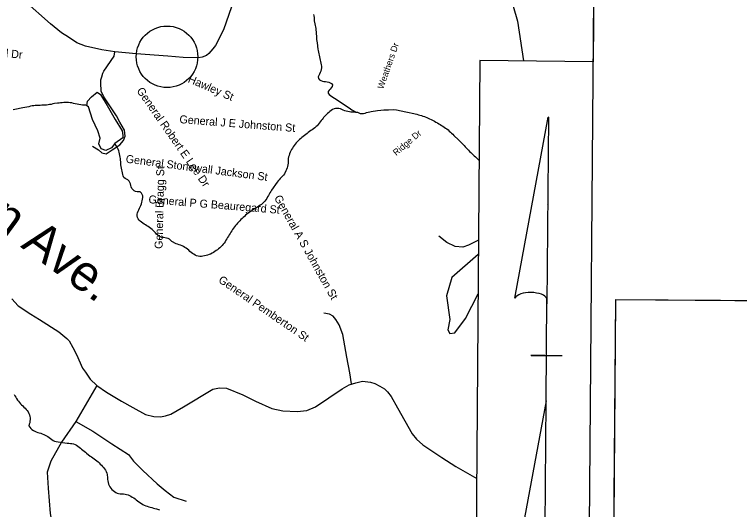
# Model space of a CAD drawing. Extents: x 1379453 to 1387082, y 594364 to 596664.
# Drawn here: x 1380505.6 to 1380802.6, y 595868.7 to 596071.5 of the extents above; entities that cross this region are included whole.
import ezdxf

# ---------------------------------------------------------------- set-up
doc = ezdxf.new("R2010")
doc.units = 0
for name, color, linetype in [('Old_Level_1', 7, 'Continuous'), ('Old_Level_10', 7, 'Continuous'), ('Old_Level_11', 7, 'Continuous'), ('Old_Level_31', 7, 'Continuous'), ('Old_Level_32', 7, 'Continuous'), ('Old_Level_35', 7, 'Continuous'), ('Old_Level_50', 7, 'Continuous'), ('Old_Level_59', 7, 'Continuous'), ('Old_Level_60', 7, 'Continuous'), ('Old_Level_62', 7, 'Continuous'), ('Prop North Arrow for Plan Sheets CELL', 7, 'Continuous'), ('Sheet Clip Boundary CELL', 7, 'Continuous')]:
    doc.layers.add(name, color=color, linetype=linetype)

msp = doc.modelspace()

# ---------------------------------------------------------------- linework, layer by layer
at = {"layer": 'Old_Level_1'}
msp.add_line((1380745.81, 596434.81), (1380740.66, 595820.56), dxfattribs=at)
at = {"layer": 'Old_Level_31'}
msp.add_line((1380723.86, 595993.71), (1380723.86, 595993.71), dxfattribs=at)
at = {"layer": 'Old_Level_32'}
for points in [[(1380690.45, 596156.89), (1380691.25, 596150.45), (1380692.03, 596143.95), (1380693.97, 596136.6), (1380696.43, 596125.28), (1380699.09, 596114.97), (1380701.97, 596103.75), (1380703.91, 596095.29), (1380705.73, 596089.1), (1380708.34, 596080.29), (1380711.67, 596068.72), (1380714.14, 596052.46)], [(1380594.44, 596074.6), (1380592.23, 596068.33), (1380591.17, 596065.24), (1380587.93, 596058.83), (1380586.84, 596057.4), (1380585.12, 596055.55), (1380584.19, 596054.73), (1380582.44, 596054.02), (1380580.92, 596053.71), (1380574.65, 596053.92), (1380568.42, 596054.42), (1380555.47, 596055.44), (1380546.72, 596056.16), (1380541.28, 596057.06), (1380534.67, 596058.53), (1380531.08, 596059.96), (1380527.63, 596062.24), (1380524.79, 596064.03), (1380520.37, 596067.67), (1380509.57, 596077.25)], [(1380504.4, 595955.07), (1380507.06, 595952.16), (1380512.24, 595948.74), (1380515.84, 595946.5), (1380523.75, 595941.56), (1380527.06, 595938.8), (1380527.97, 595937.78), (1380529.42, 595935.04), (1380530.94, 595932.25), (1380533.36, 595926.58), (1380534.67, 595924.97), (1380536.49, 595922.17), (1380539.34, 595919.56), (1380543.2, 595916.74), (1380549.41, 595913.11), (1380554.01, 595910.49), (1380559.21, 595907.66), (1380562.61, 595906.75), (1380565.34, 595906.73), (1380567.42, 595907.15), (1380569.61, 595907.79), (1380574.78, 595910.81), (1380586.85, 595918.07), (1380589.62, 595918.54), (1380592.39, 595918.43), (1380599.07, 595915.68), (1380604.27, 595913.05), (1380610.96, 595910.11), (1380615.46, 595909.18), (1380621.39, 595908.83), (1380625.39, 595909.3), (1380628.84, 595910.8), (1380639.77, 595918.13), (1380642.63, 595919.85), (1380645.41, 595920.66), (1380648.21, 595921.34), (1380651.49, 595920.87), (1380653.25, 595920.29), (1380655.29, 595919.28), (1380657.12, 595918.17), (1380658.44, 595916.97), (1380659.86, 595914.97), (1380662.48, 595910.38), (1380668.44, 595899.69), (1380670.27, 595897.59), (1380672.91, 595895.18), (1380680.59, 595890), (1380686.41, 595886.3), (1380694.93, 595881.48)]]:
    msp.add_lwpolyline(points, dxfattribs=at)
msp.add_lwpolyline([(1380751.9, 595954.74), (1382700.35, 595938.42), (1382692.2, 594965.67), (1380743.75, 594981.99)], close=True, dxfattribs=at)
msp.add_circle((1380568.05, 596054.17), 12.61, dxfattribs=at)
at = {"layer": 'Old_Level_35'}
msp.add_line((1380539.34, 595919.56), (1380530.74, 595904.71), dxfattribs=at)
for points in [[(1380537.49, 596017.61), (1380539.92, 596016.02), (1380541.33, 596014.78), (1380543.08, 596014.49), (1380545.6, 596016.02), (1380548.71, 596018.17), (1380550.2, 596019.89), (1380550.89, 596021.64), (1380550.68, 596024.08), (1380548.71, 596027.37), (1380547.4, 596030.01), (1380542.16, 596037.78), (1380541.03, 596040.09), (1380540.95, 596043.47), (1380540.99, 596044.7), (1380541.27, 596046), (1380541.72, 596047.53), (1380542.14, 596048.3), (1380546.45, 596054.4), (1380546.72, 596056.16)], [(1380695.64, 595979.05), (1380691.61, 595976.94), (1380689.26, 595976.2), (1380686.15, 595976.46), (1380682.68, 595978.16), (1380679.47, 595980.73)], [(1380643.6, 595920.14), (1380642.89, 595924.65), (1380641.71, 595931.12), (1380640.03, 595940.41), (1380638.55, 595944.38), (1380637.25, 595946.58), (1380636.09, 595947.9), (1380634.67, 595948.74), (1380632.28, 595949.21)], [(1380530.74, 595904.71), (1380524.77, 595896.26), (1380520.47, 595888.46), (1380518.89, 595883.99), (1380519.29, 595877.51), (1380520.23, 595867.05), (1380522.06, 595855.7), (1380521.37, 595850.11), (1380520.51, 595847.38), (1380517.12, 595840.68), (1380515.35, 595838.27)], [(1380530.74, 595904.71), (1380537.6, 595900.84), (1380545.42, 595895.67), (1380552.2, 595891.22), (1380554.26, 595888.55), (1380558.15, 595884.7), (1380564.03, 595879.26), (1380567.35, 595876.5), (1380570.88, 595873.81), (1380575.84, 595872.11)]]:
    msp.add_lwpolyline(points, dxfattribs=at)
at = {"layer": 'Old_Level_50'}
msp.add_line((1380723.94, 595994.19), (1380723.94, 595994.19), dxfattribs=at)
at = {"layer": 'Old_Level_59'}
for points in [[(1380628.1, 596071.55), (1380628.22, 596070.9), (1380628.3, 596070.25), (1380628.32, 596069.59), (1380628.39, 596068.94), (1380628.62, 596067.67), (1380628.75, 596067.03), (1380628.92, 596066.4), (1380628.99, 596065.75), (1380629.2, 596063.79), (1380629.25, 596062.5), (1380629.36, 596061.22), (1380629.51, 596059.95), (1380629.85, 596057.35), (1380629.97, 596056.7), (1380630.1, 596056.06), (1380630.24, 596055.42), (1380630.39, 596054.78), (1380630.55, 596054.14), (1380630.7, 596053.5), (1380630.83, 596052.86), (1380630.98, 596052.22), (1380631.1, 596051.57), (1380631.22, 596050.93), (1380631.29, 596050.28), (1380631.28, 596049.62), (1380631.21, 596048.96), (1380631.08, 596048.32), (1380630.85, 596047.71), (1380630.56, 596047.12), (1380630.26, 596046.53), (1380630.05, 596045.92), (1380630.14, 596045.27), (1380630.55, 596044.75), (1380631.1, 596044.41), (1380631.72, 596044.17), (1380632.37, 596044.06), (1380633.03, 596044.01), (1380633.68, 596043.93), (1380634.32, 596043.78), (1380634.95, 596043.57), (1380635.49, 596043.24), (1380635.8, 596042.65), (1380635.69, 596041.99), (1380635.35, 596041.43), (1380634.9, 596040.95), (1380634.45, 596040.47), (1380634.12, 596039.91), (1380634.12, 596039.27), (1380634.5, 596038.72), (1380635, 596038.29), (1380635.57, 596037.96), (1380637.77, 596036.55), (1380639.95, 596035.08), (1380642.66, 596033.23), (1380643.2, 596032.87), (1380643.75, 596032.51), (1380644.31, 596032.16), (1380645.4, 596031.47)], [(1380645.4, 596031.47), (1380646.05, 596031.47), (1380646.65, 596031.2), (1380647.26, 596030.96), (1380647.92, 596030.91), (1380648.56, 596031.01), (1380649.2, 596031.15), (1380649.84, 596031.32), (1380650.48, 596031.48), (1380651.12, 596031.64), (1380651.75, 596031.78), (1380654.34, 596032.17), (1380655.63, 596032.3), (1380656.93, 596032.39), (1380658.87, 596032.49), (1380660.82, 596032.57), (1380662.11, 596032.39), (1380665.97, 596031.65), (1380667.25, 596031.4), (1380668.51, 596031.15), (1380669.15, 596030.99), (1380669.78, 596030.82), (1380670.41, 596030.64), (1380671.04, 596030.47), (1380671.68, 596030.28), (1380672.31, 596030.09), (1380672.93, 596029.9), (1380673.55, 596029.69), (1380674.74, 596029.19), (1380677.1, 596028.06), (1380677.68, 596027.75), (1380678.25, 596027.43), (1380678.82, 596027.1), (1380679.39, 596026.77), (1380679.96, 596026.44), (1380680.51, 596026.09), (1380681.06, 596025.74), (1380681.61, 596025.37), (1380682.15, 596024.99), (1380682.68, 596024.6), (1380683.19, 596024.2), (1380683.69, 596023.77), (1380684.18, 596023.34), (1380684.66, 596022.88), (1380685.13, 596022.43), (1380685.59, 596021.96), (1380687.45, 596020.1), (1380689.75, 596017.79), (1380690.2, 596017.31), (1380690.66, 596016.83), (1380691.12, 596016.37), (1380691.58, 596015.9), (1380692.04, 596015.44), (1380692.51, 596014.97), (1380692.98, 596014.51), (1380693.45, 596014.06), (1380693.93, 596013.61), (1380694.41, 596013.17), (1380695.87, 596011.89)], [(1380505.37, 595915.8), (1380505.7, 595915.24), (1380506.04, 595914.68), (1380506.39, 595914.12), (1380506.75, 595913.57), (1380507.14, 595913.04), (1380507.57, 595912.55), (1380508.01, 595912.06), (1380508.47, 595911.59), (1380508.93, 595911.12), (1380509.4, 595910.65), (1380509.86, 595910.18), (1380510.3, 595909.7), (1380510.73, 595909.21), (1380511.12, 595908.68), (1380511.42, 595908.1), (1380511.69, 595907.49), (1380511.87, 595906.86), (1380511.93, 595906.21), (1380511.93, 595905.55), (1380511.89, 595904.9), (1380511.82, 595904.24), (1380511.58, 595903.63), (1380511.49, 595902.97), (1380511.78, 595902.41), (1380512.22, 595901.9), (1380512.72, 595901.46), (1380513.27, 595901.1), (1380513.85, 595900.78), (1380514.45, 595900.52), (1380515.08, 595900.32), (1380515.72, 595900.17), (1380516.35, 595899.98), (1380518.14, 595899.23), (1380518.73, 595898.93), (1380519.27, 595898.56), (1380519.8, 595898.17), (1380520.32, 595897.77), (1380520.84, 595897.38), (1380521.4, 595897.01), (1380521.99, 595896.75), (1380522.63, 595896.6), (1380525.21, 595896.13), (1380527.14, 595895.88), (1380527.8, 595895.85), (1380528.46, 595895.8), (1380529.11, 595895.73), (1380529.75, 595895.59), (1380530.37, 595895.36), (1380530.94, 595895.03), (1380531.48, 595894.66), (1380532.01, 595894.28)], [(1380532.01, 595894.28), (1380532.54, 595893.89), (1380533.06, 595893.48), (1380533.57, 595893.07), (1380534.08, 595892.66), (1380534.6, 595892.24), (1380535.06, 595891.78), (1380536.6, 595890.59), (1380537.15, 595890.23), (1380537.7, 595889.87), (1380538.25, 595889.5), (1380538.78, 595889.12), (1380539.29, 595888.71), (1380539.77, 595888.27), (1380540.25, 595887.81), (1380540.71, 595887.35), (1380541.17, 595886.87), (1380541.62, 595886.39), (1380542.05, 595885.9), (1380542.45, 595885.38), (1380542.79, 595884.82), (1380543.09, 595884.23), (1380543.34, 595883.62), (1380543.48, 595882.99), (1380543.69, 595881.71), (1380543.67, 595881.05), (1380543.78, 595880.4), (1380543.9, 595879.75), (1380544.07, 595879.12), (1380544.3, 595878.51), (1380544.63, 595877.94), (1380545.01, 595877.4), (1380545.45, 595876.9), (1380545.94, 595876.47), (1380546.48, 595876.09), (1380547.03, 595875.73), (1380547.59, 595875.4), (1380548.22, 595875.2), (1380548.87, 595875.16), (1380549.53, 595875.16), (1380550.19, 595875.14), (1380552.1, 595874.74), (1380552.68, 595874.46), (1380553.26, 595874.15), (1380553.83, 595873.81), (1380554.39, 595873.46), (1380554.94, 595873.11), (1380555.47, 595872.72), (1380555.98, 595872.31), (1380556.51, 595871.91), (1380557.57, 595871.13), (1380558.12, 595870.77), (1380558.71, 595870.49), (1380559.33, 595870.27), (1380559.95, 595870.06), (1380560.57, 595869.86), (1380561.2, 595869.67), (1380561.83, 595869.49), (1380562.46, 595869.31), (1380563.1, 595869.13), (1380563.73, 595868.96), (1380565, 595868.61)]]:
    msp.add_lwpolyline(points, dxfattribs=at)
at = {"layer": 'Old_Level_60'}
for points in [[(1380695.59, 595973.14), (1380684.81, 595963.81), (1380682.59, 595956.25), (1380683.95, 595946.5)], [(1380683.95, 595946.5), (1380683.16, 595942.28), (1380684, 595940.86), (1380685.98, 595941.13), (1380690.31, 595946.97), (1380695.48, 595957.08)]]:
    msp.add_lwpolyline(points, dxfattribs=at)
at = {"layer": 'Old_Level_62'}
for points in [[(1380535.21, 596034.12), (1380535.47, 596035.97), (1380537.1, 596037.81), (1380539.43, 596039.64), (1380540.81, 596038.7), (1380543.55, 596034.28), (1380546.74, 596028.47), (1380549.7, 596023.81), (1380549.92, 596021.96), (1380549.92, 596021.03), (1380546.7, 596018.7)], [(1380534.8, 596034.4), (1380534.14, 596034.41), (1380533.48, 596034.43), (1380529.66, 596035.09), (1380529.04, 596035.29), (1380528.39, 596035.37), (1380527.74, 596035.44), (1380527.08, 596035.48), (1380526.43, 596035.47), (1380525.78, 596035.43), (1380525.12, 596035.37), (1380524.46, 596035.31), (1380523.81, 596035.23), (1380523.16, 596035.15), (1380521.89, 596034.98), (1380521.24, 596034.85), (1380520.6, 596034.7), (1380519.96, 596034.57), (1380519.31, 596034.48), (1380518.65, 596034.42), (1380518, 596034.37), (1380517.35, 596034.33), (1380516.69, 596034.3), (1380516.03, 596034.27), (1380515.37, 596034.24), (1380514.72, 596034.21), (1380514.06, 596034.16), (1380513.41, 596034.1), (1380512.76, 596034.03), (1380512.12, 596033.91), (1380511.49, 596033.74), (1380508.91, 596033.21), (1380505.7, 596032.55), (1380505.05, 596032.43)], [(1380546.7, 596018.7), (1380545.25, 596016.9), (1380542.93, 596015.76), (1380541.08, 596016.48), (1380540.17, 596018.57), (1380540.66, 596020.88), (1380539.76, 596023.89), (1380537.48, 596028.54), (1380535.91, 596033.65), (1380535.21, 596034.12)], [(1380645.4, 596031.47), (1380644.08, 596031.52), (1380643.43, 596031.55), (1380642.77, 596031.6), (1380641.51, 596031.86), (1380640.88, 596032.04), (1380640.28, 596032.3), (1380639.71, 596032.63), (1380639.08, 596032.83), (1380638.43, 596032.99), (1380637.78, 596033.06), (1380637.14, 596033), (1380636.5, 596032.81), (1380635.89, 596032.55), (1380635.33, 596032.22), (1380634.79, 596031.83), (1380634.3, 596031.4), (1380633.82, 596030.96), (1380633.35, 596030.5), (1380632.88, 596030.03), (1380632.43, 596029.55), (1380632.17, 596029.26)], [(1380632.17, 596029.26), (1380632, 596029.06), (1380631.58, 596028.55), (1380631.19, 596028.03), (1380630.81, 596027.49), (1380630.43, 596026.95), (1380630.03, 596026.43), (1380629.58, 596025.95), (1380629.19, 596025.6)], [(1380629.19, 596025.6), (1380628.57, 596025.11), (1380628.05, 596024.71), (1380627.53, 596024.32), (1380627, 596023.93), (1380626.47, 596023.53), (1380625.95, 596023.14), (1380625.42, 596022.75), (1380624.89, 596022.36), (1380624.37, 596021.96), (1380623.86, 596021.56), (1380623.34, 596021.15), (1380622.84, 596020.73), (1380622.35, 596020.29), (1380621.87, 596019.84), (1380621.4, 596019.38), (1380620.96, 596018.9), (1380620.53, 596018.4), (1380620.14, 596017.87), (1380619.76, 596017.33), (1380619.4, 596016.78), (1380619.05, 596016.22), (1380618.74, 596015.64), (1380618.48, 596015.04), (1380618.25, 596014.43), (1380618.04, 596013.8), (1380617.87, 596013.17), (1380617.75, 596012.53), (1380617.73, 596011.87), (1380617.73, 596011.21), (1380617.72, 596010.55), (1380617.6, 596009.91), (1380617.44, 596009.27), (1380617.26, 596008.63), (1380617.03, 596008.02), (1380616.74, 596007.43), (1380616.15, 596006.25), (1380615.79, 596005.71), (1380615.34, 596005.24), (1380614.87, 596004.78), (1380614.39, 596004.32), (1380613.95, 596003.84), (1380613.53, 596003.33), (1380613.13, 596002.81), (1380610.92, 595999.56), (1380610.57, 595999.01), (1380610.23, 595998.44), (1380609.91, 595997.87), (1380609.58, 595997.3), (1380609.24, 595996.74), (1380608.9, 595996.18), (1380608.54, 595995.63), (1380608.15, 595995.1), (1380607.72, 595994.61), (1380607.25, 595994.15), (1380606.73, 595993.73), (1380606.2, 595993.36), (1380605.66, 595992.99), (1380605.11, 595992.63), (1380604.56, 595992.27), (1380604, 595991.92), (1380603.45, 595991.56), (1380602.9, 595991.2), (1380602.36, 595990.84), (1380601.82, 595990.46), (1380601.29, 595990.07), (1380600.78, 595989.66), (1380600.27, 595989.24), (1380599.77, 595988.81), (1380599.28, 595988.38), (1380598.79, 595987.94), (1380598.33, 595987.48), (1380597.87, 595987.01), (1380597.43, 595986.52), (1380596.99, 595986.04), (1380596.55, 595985.54), (1380596.13, 595985.04), (1380595.72, 595984.52), (1380595.33, 595984), (1380594.94, 595983.47), (1380594.58, 595982.92), (1380594.22, 595982.37), (1380593.88, 595981.81), (1380593.54, 595981.25), (1380593.2, 595980.68), (1380592.87, 595980.12), (1380592.54, 595979.55), (1380592.2, 595978.99), (1380591.86, 595978.43), (1380591.51, 595977.87), (1380591.11, 595977.35), (1380590.66, 595976.87), (1380590.2, 595976.4), (1380589.71, 595975.96), (1380589.2, 595975.56), (1380588.67, 595975.16), (1380588.14, 595974.78), (1380587.6, 595974.41), (1380587.05, 595974.04), (1380586.49, 595973.7)], [(1380548.62, 596014.41), (1380548.45, 596015.05), (1380548.24, 596015.67), (1380548.02, 596016.29), (1380547.75, 596016.89), (1380547.44, 596017.47), (1380547.11, 596018.03), (1380546.7, 596018.7)], [(1380586.49, 595973.7), (1380585.91, 595973.38), (1380585.31, 595973.12), (1380584.69, 595972.91), (1380584.06, 595972.74), (1380583.41, 595972.6), (1380582.76, 595972.49), (1380582.11, 595972.4), (1380581.45, 595972.41), (1380580.81, 595972.52), (1380580.17, 595972.7), (1380579.56, 595972.95), (1380579, 595973.28), (1380578.45, 595973.65), (1380577.93, 595974.04), (1380577.41, 595974.45), (1380576.92, 595974.89), (1380576.45, 595975.35), (1380575.94, 595975.76), (1380575.39, 595976.11), (1380574.81, 595976.43), (1380574.23, 595976.73), (1380573.63, 595977), (1380573.01, 595977.21), (1380572.36, 595977.36), (1380571.76, 595977.6), (1380570.06, 595978.54), (1380569.57, 595978.98), (1380569.08, 595979.43), (1380568.54, 595979.79), (1380567.9, 595979.93), (1380566.63, 595980.17), (1380565.98, 595980.21), (1380565.33, 595980.38), (1380564.76, 595980.69), (1380564.26, 595981.11), (1380563.79, 595981.56), (1380563.32, 595982.02), (1380562.86, 595982.49), (1380562.39, 595982.96), (1380561.91, 595983.41), (1380561.42, 595983.85), (1380560.91, 595984.25), (1380560.37, 595984.62), (1380559.81, 595984.97), (1380559.24, 595985.31), (1380558.68, 595985.65), (1380558.12, 595986), (1380557.59, 595986.38), (1380557.07, 595986.8), (1380556.59, 595987.25), (1380556.18, 595987.76), (1380555.93, 595988.36), (1380555.82, 595989.02), (1380555.84, 595989.68), (1380556, 595990.31), (1380556.24, 595990.92), (1380556.51, 595991.52), (1380556.82, 595992.1), (1380557.1, 595992.69), (1380557.33, 595993.31), (1380557.53, 595993.94), (1380557.71, 595994.57), (1380557.87, 595995.21), (1380557.99, 595995.85), (1380558.07, 595996.51), (1380558.08, 595997.17), (1380557.92, 595997.79), (1380557.56, 595998.35), (1380557.09, 595998.82), (1380556.45, 595998.9), (1380555.78, 595998.91), (1380555.13, 595998.96), (1380554.55, 595999.28), (1380554.1, 595999.76), (1380553.69, 596000.27), (1380553.38, 596000.84), (1380553.22, 596001.49), (1380553.08, 596002.11), (1380552.8, 596002.71), (1380552.47, 596003.28), (1380552.03, 596003.75), (1380551.44, 596004.06), (1380550.85, 596004.34), (1380550.34, 596004.75), (1380550.12, 596005.37), (1380549.95, 596006), (1380549.8, 596006.64), (1380549.66, 596007.28), (1380549.52, 596007.92), (1380549.38, 596008.57), (1380549.25, 596009.21), (1380549.18, 596009.86), (1380549.17, 596010.51), (1380549.1, 596011.17), (1380549.02, 596011.82), (1380548.94, 596012.47), (1380548.85, 596013.12), (1380548.75, 596013.77), (1380548.62, 596014.41)]]:
    msp.add_lwpolyline(points, dxfattribs=at)
at = {"layer": 'Prop North Arrow for Plan Sheets CELL'}
for p, q in [((1380710.54, 595955.36), (1380724.28, 596029.4)), ((1380724.36, 596029.4), (1380723.72, 595952.92)), ((1380724.36, 596029.4), (1380724.28, 596029.4)), ((1380724.36, 596029.4), (1380724.28, 596029.4)), ((1380723.38, 595913.25), (1380723.73, 595955.16)), ((1380723.72, 595952.92), (1380723.73, 595955.08)), ((1380717.14, 595931.86), (1380717.06, 595931.86)), ((1380722.82, 595931.81), (1380717.14, 595931.86)), ((1380717.22, 595931.86), (1380730.02, 595931.75)), ((1380723.38, 595913.25), (1380709.39, 595837.76)), ((1380722.83, 595837.97), (1380723.38, 595913.25))]:
    msp.add_line(p, q, dxfattribs=at)
msp.add_ellipse((1380717.15, 595954.51), major_axis=(6.77, -0.1), ratio=0.461098, start_param=0.216388, end_param=2.908219, dxfattribs=at)
at = {"layer": 'Sheet Clip Boundary CELL'}
for points in [[(1379993.85, 596441.11), (1380745.81, 596434.81), (1380742.6, 596052.18), (1380696.17, 596052.63), (1380694.49, 595820.94), (1379988.71, 595826.86)], [(1380751.9, 595954.74), (1381159.38, 595952.2), (1381397.04, 595433.8), (1382327.02, 595438.14), (1382414.39, 595940.93), (1382700.35, 595938.54), (1382692.2, 594965.67), (1380744.56, 594981.99)]]:
    msp.add_lwpolyline(points, close=True, dxfattribs=at)

# ---------------------------------------------------------------- texts
at = {"layer": 'Old_Level_10'}
for s, height, rotation, p in [('Weathers Dr', 2.6247, 70.7146, (1380656.62, 596040.75)), ('Ethel Dr', 3.281, 354.2709, (1380492.89, 596054.96)), ('Hawley St', 3.281, 336.7084, (1380576.34, 596043.86)), ('General Robert E Lee Dr', 3.2808, 304.8589, (1380555.42, 596040.27)), ('General J E Johnston St', 3.2808, 355.6298, (1380573.04, 596027.02)), ('Ridge Dr', 2.625, 40.2528, (1380661.97, 596013.5)), ('General Stonewall Jackson St', 3.2808, 352.6011, (1380550.99, 596010.84)), ('General Bragg St', 3.2808, 88.7392, (1380566.22, 595975.47)), ('General P G Beauregard St', 3.2808, 355.3582, (1380560.37, 595994.22)), ('General A S Johnston St', 3.2808, 299.3277, (1380611.81, 595996.42)), ('General Pemberton St', 3.2808, 325.5216, (1380588.81, 595962.07))]:
    msp.add_text(s, height=height, rotation=rotation, dxfattribs=at).set_placement(p)
at = {"layer": 'Old_Level_11'}
msp.add_text('Woodlawn Ave.', height=14.7638, rotation=323.7208, dxfattribs=at).set_placement((1380429.01, 596034.18))

doc.saveas('drawing.dxf')
